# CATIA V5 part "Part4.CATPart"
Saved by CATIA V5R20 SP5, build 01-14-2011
Part number: 凸缘压板
Bounding box of the stored display mesh (mm): x -40 to 40, y -10 to 40, z 0 to 40
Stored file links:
  E:\scc\Part4.CATPart
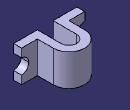
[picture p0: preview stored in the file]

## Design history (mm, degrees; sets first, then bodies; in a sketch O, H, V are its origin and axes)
Body1 (main body)
  Sketch1 on xy-plane, origin (0, 0, 0), H (1, 0, 0), V (0, 1, 0)
    line L1 (-10, 20) -> (-10, -10)
    line L2 (-10, -10) -> (-40, -10)
    line L3 (-40, -10) -> (-40, 0)
    point P4 (-40, 0)
    line L4 (40, -10) -> (40, 0)
    point P6 (40, 0)
    line L5 (40, 0) -> (20, 0)
    line L6 (20, 0) -> (20, 20)
    arc A1 centre (0, 20) radius 10 from (10, 20) to (-10, 20) ccw
    point P9 (0, 20)
    arc A2 centre (0, 20) radius 20 from (20, 20) to (-20, 20) ccw
    line L7 (10, 20) -> (10, -10)
    point P11 (10, -10)
    line L8 (10, -10) -> (40, -10)
    line L9 (-20, 20) -> (-20, 0)
    point P13 (-20, 0)
    line L10 (-20, 0) -> (-40, 0)
    distance L5 P9 = 20
    radius A1 = 10
    radius A2 = 20
    distance O L4 = 40
    distance O L3 = 40
    length L4 = 10
    vertical: L1 V, L3 V, L4 V, L6 V
    horizontal: L2 H, L5 H, L8 H, L10 H
    coincidence: P4 H, P6 H, P9 V, P11 L2, P13 H
    tangency: A1 L1, A2 L6, L7 A1, L9 A2
  Pad1: profile Sketch1, direction (0, 0, 1), length 40
  Sketch2 on face of Pad1 from Sketch1.L5, origin (0, 0, 0), H (-1, 0, 0), V (0, 0, 1)
    circle A1 centre (-40.2209, 19.9214) radius 9.4823
  Pocket1: profile Sketch2, direction (0, -1, 0), length 40
  Mirror1: of Pocket1, about yz-plane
